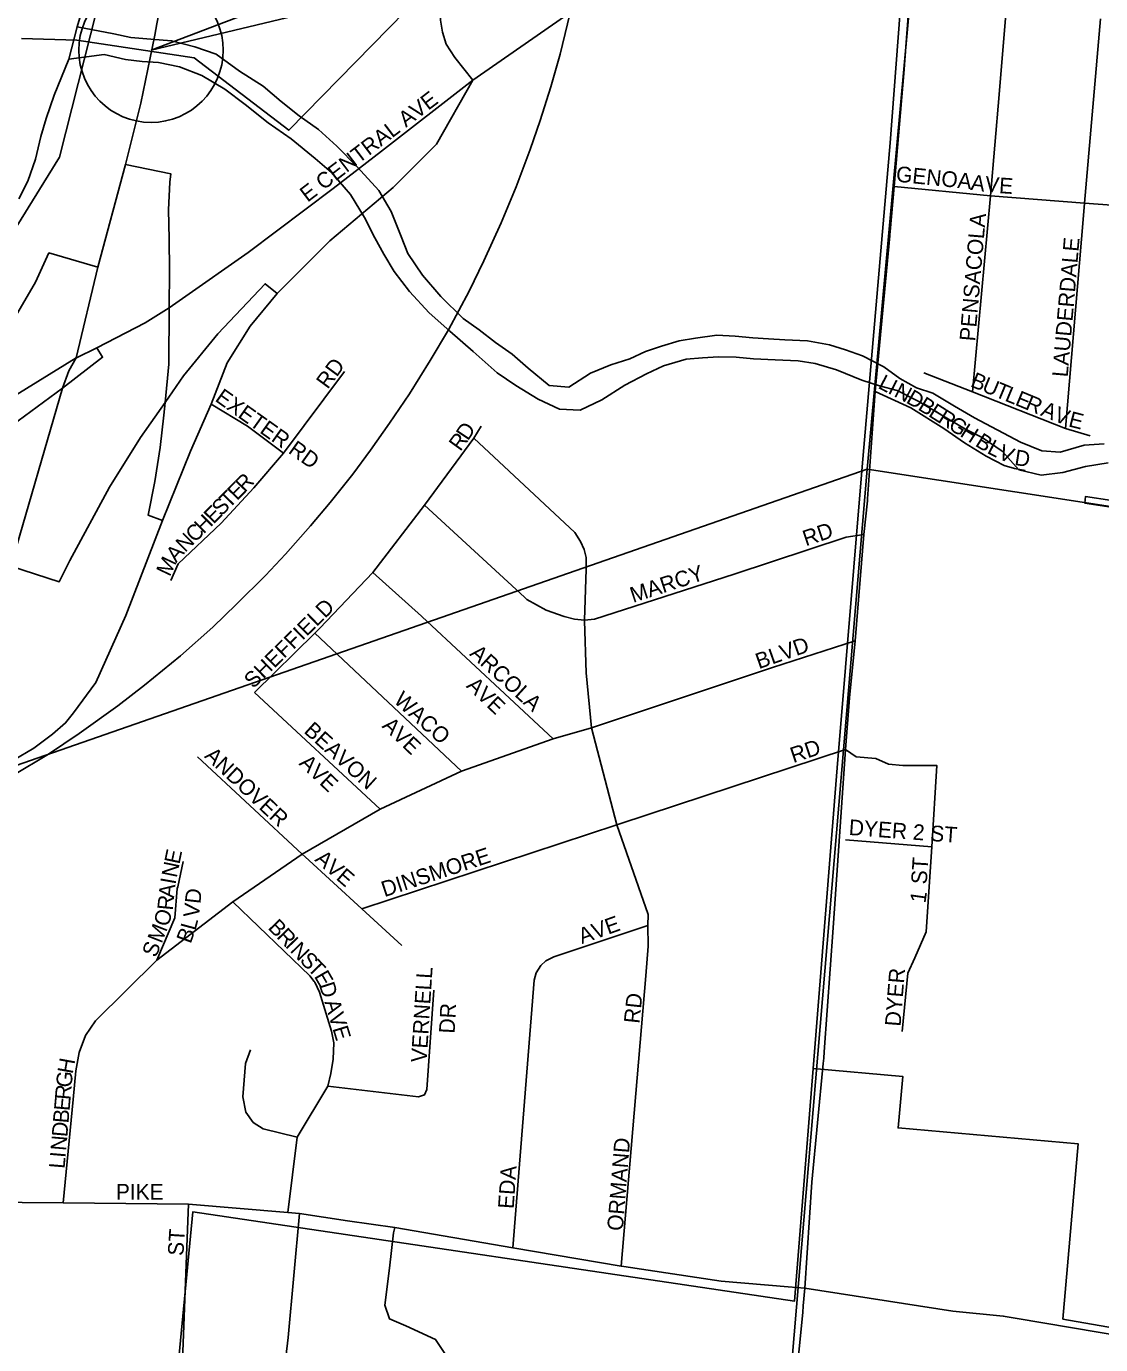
# Model space of a CAD drawing. Extents: x -209 to 4852, y 0 to 905.
# Drawn here: x 505.3 to 518.26, y 261.1 to 277 of the extents above; entities that cross this region are included whole.
import ezdxf

# ---------------------------------------------------------------- set-up
doc = ezdxf.new("R2010")
doc.units = 0
for name, color, linetype in [('GM_X_Airport_Location_Class_2', 7, 'Continuous'), ('GM_X_Airport_Location_Class_3', 7, 'Continuous'), ('GM_X_County_Road', 7, 'Continuous'), ('GM_X_County_Road_Text', 7, 'Continuous'), ('GM_X_County_Subdivision_Text', 7, 'Continuous'), ('GM_X_Interstate_Location', 7, 'Continuous'), ('GM_X_Major_Lake', 7, 'Continuous'), ('GM_X_Minor_River', 7, 'Continuous'), ('GM_X_Rail_Line', 7, 'Continuous'), ('GM_X_Rail_Line_Text', 7, 'Continuous'), ('GM_X_Township_Text', 7, 'Continuous'), ('GM_X_US_Location', 7, 'Continuous'), ('GM_X_US_Route', 7, 'Continuous'), ('SH_Text', 7, 'Continuous')]:
    doc.layers.add(name, color=color, linetype=linetype)

msp = doc.modelspace()

# ---------------------------------------------------------------- linework, layer by layer
at = {"layer": 'GM_X_Airport_Location_Class_2'}
for points in [[(510.682, 276.351), (512.37, 277.526), (513.786, 278.834), (515.257, 280.142), (516.225, 280.826)], [(517.032, 276.181), (517.176, 277.923), (517.181, 277.978)], [(510.682, 276.351), (510.467, 276.626), (510.361, 276.786), (510.317, 276.933), (510.292, 277.077), (510.296, 277.434), (510.322, 277.841)], [(518.05, 274.719), (518.062, 274.869), (518.255, 277.091)], [(506.942, 271.041), (507.279, 271.877), (507.527, 272.443), (507.722, 272.94), (507.999, 273.386), (508.325, 273.779), (508.957, 274.412), (509.723, 275.057), (510.247, 275.582), (510.682, 276.351)], [(510.682, 276.351), (509.582, 275.496)], [(516.712, 272.591), (516.93, 274.958), (517.032, 276.181)], [(509.582, 275.496), (509.001, 275.045), (507.973, 274.272), (507.182, 273.718)], [(515.765, 275.071), (516.93, 274.958), (518.062, 274.869), (518.665, 274.825)], [(517.833, 272.148), (518.05, 274.719)], [(507.182, 273.718), (507.02, 273.605), (506.731, 273.426), (506.148, 273.122), (505.902, 273.003)], [(505.902, 273.003), (505.899, 273.001), (504.972, 272.432)], [(507.039, 270.316), (507.131, 270.516), (507.65, 271.009), (508.042, 271.435), (508.4, 271.851), (509.137, 272.837)], [(516.126, 272.821), (516.712, 272.591), (517.833, 272.148), (518.129, 272.062)], [(515.536, 272.596), (515.967, 272.4), (516.364, 272.149), (516.615, 271.975), (516.878, 271.816), (517.092, 271.702), (517.217, 271.666), (517.345, 271.641)], [(507.527, 272.443), (507.966, 272.176), (508.4, 271.851)], [(508.837, 269.74), (509.477, 270.413), (510.1, 271.225), (510.694, 272.033), (510.786, 272.178)], [(512.03, 269.829), (512.03, 269.836), (512.05, 270.452), (512.052, 270.593), (512.025, 270.691), (511.983, 270.788), (511.914, 270.896), (510.694, 272.033)], [(510.1, 271.225), (511.309, 270.113)], [(504.181, 267.746), (504.255, 267.765), (504.621, 267.902), (505.144, 268.148), (505.388, 268.293), (505.615, 268.461), (505.771, 268.598), (505.868, 268.719), (506.135, 269.086), (506.498, 269.893), (506.942, 271.041)], [(511.309, 270.113), (511.337, 270.087), (511.567, 269.959), (511.784, 269.883), (511.912, 269.851), (512.03, 269.836), (512.151, 269.848), (513.835, 270.393), (515.188, 270.839), (515.4, 270.871)], [(510.065, 269.886), (509.477, 270.413)], [(511.653, 268.405), (510.074, 269.877), (510.065, 269.886)], [(512.474, 262.043), (512.77, 265.547), (512.797, 265.904), (512.795, 266.153), (512.797, 266.284), (512.42, 267.366), (512.114, 268.539), (512.05, 269.202), (512.03, 269.829)], [(508.052, 268.965), (508.78, 269.679), (508.837, 269.74)], [(510.547, 268.015), (508.78, 269.679)], [(505.743, 262.805), (505.863, 264.053), (505.896, 264.4), (505.937, 264.619), (506.011, 264.825), (506.134, 265.003), (506.874, 265.733), (507.79, 266.439), (508.625, 267.014), (509.566, 267.557), (510.547, 268.015), (511.653, 268.405), (512.114, 268.539), (514.297, 269.264), (515.294, 269.589)], [(509.566, 267.557), (508.052, 268.965)], [(508.663, 266.98), (508.625, 267.014), (507.361, 268.189)], [(512.457, 267.378), (515.181, 268.275)], [(515.863, 264.876), (515.93, 265.578), (516.014, 265.764), (516.152, 266.077), (516.22, 267.104), (516.282, 268.082), (515.872, 268.082), (515.697, 268.099), (515.546, 268.167), (515.308, 268.19), (515.181, 268.275)], [(509.344, 266.355), (512.42, 267.366), (512.457, 267.378)], [(515.181, 267.187), (516.22, 267.104)], [(507.124, 266.621), (507.189, 266.925)], [(509.826, 265.912), (509.344, 266.355), (508.663, 266.98)], [(506.874, 265.733), (507.091, 266.247), (507.119, 266.601), (507.124, 266.621)], [(508.771, 265.479), (508.719, 265.547), (507.79, 266.439)], [(511.167, 262.265), (511.423, 265.492), (511.447, 265.58), (511.503, 265.67), (511.564, 265.726), (511.66, 265.776), (512.795, 266.153)], [(508.453, 262.692), (508.564, 263.6), (508.934, 264.213), (508.972, 264.366), (508.998, 264.54), (509.008, 264.736), (508.981, 264.879), (508.833, 265.347), (508.778, 265.47), (508.771, 265.479)], [(508.934, 264.213), (510.028, 264.085), (510.102, 264.109), (510.129, 264.174), (510.214, 265.374)], [(497.772, 264.73), (498.092, 264.608), (499.518, 263.953), (500.869, 263.334), (501.741, 262.94), (502.023, 262.883), (502.736, 262.863), (503.261, 262.828), (505.743, 262.805), (507.256, 262.792), (508.453, 262.692), (508.594, 262.677), (509.173, 262.591), (509.742, 262.508), (511.167, 262.265), (512.474, 262.043), (512.507, 262.038)], [(508.564, 263.6), (508.154, 263.699), (508.034, 263.778), (507.946, 263.901), (507.908, 264.085), (507.94, 264.487), (508.002, 264.652)], [(507.248, 262.589), (507.256, 262.792)], [(512.507, 262.038), (513.68, 261.863), (514.489, 261.793)]]:
    msp.add_lwpolyline(points, dxfattribs=at)
at = {"layer": 'GM_X_County_Road'}
msp.add_line((505.912, 276.995), (505.81, 276.606), dxfattribs=at)
for points in [[(518.3, 271.966), (518.057, 271.948), (517.767, 271.862), (517.547, 271.882), (517.291, 271.986), (516.735, 272.278), (516.495, 272.42), (516.233, 272.577), (516.037, 272.642), (515.834, 272.752), (515.64, 272.893), (515.384, 273.027), (515.181, 273.1), (514.985, 273.157), (514.72, 273.208), (514.447, 273.221), (514.25, 273.232), (514.06, 273.243), (513.848, 273.263), (513.629, 273.275), (513.37, 273.241), (513.172, 273.207), (512.958, 273.143), (512.767, 273.078), (512.576, 272.99), (512.347, 272.919), (512.102, 272.817), (511.841, 272.647), (511.606, 272.667), (511.352, 272.877), (511.158, 273.048), (510.956, 273.189), (510.762, 273.338), (510.567, 273.478), (510.299, 273.742), (510.077, 273.998), (509.9, 274.26), (509.82, 274.467), (509.697, 274.767), (509.55, 275.021), (509.29, 275.308), (509.045, 275.556), (508.821, 275.758), (508.589, 275.923), (508.372, 276.094), (508.156, 276.281), (507.871, 276.462), (507.587, 276.665), (507.331, 276.754), (507.051, 276.828), (506.801, 276.848), (506.559, 276.868), (506.355, 276.91), (505.912, 276.995)], [(505.81, 276.606), (506.236, 276.661), (506.493, 276.603), (506.697, 276.576), (506.894, 276.565), (507.144, 276.514), (507.415, 276.41), (507.692, 276.245), (507.939, 276.057), (508.216, 275.839), (508.493, 275.643), (508.784, 275.409), (508.978, 275.237), (509.208, 274.974), (509.377, 274.697), (509.501, 274.451), (509.611, 274.251), (509.736, 274.043), (509.921, 273.803), (510.159, 273.547), (510.405, 273.322), (510.688, 273.08), (510.979, 272.823), (511.204, 272.667), (511.474, 272.502), (511.729, 272.382), (511.98, 272.37), (512.24, 272.494), (512.517, 272.672), (512.777, 272.811), (512.984, 272.906), (513.259, 272.985), (513.456, 273.004), (513.646, 273.015), (513.859, 273.011), (514.071, 272.992), (514.329, 272.979), (514.609, 272.966), (514.813, 272.932), (515.07, 272.858), (515.378, 272.731), (515.59, 272.666), (515.801, 272.608), (516.064, 272.474), (516.334, 272.316), (516.626, 272.143), (516.829, 272.04), (517.069, 271.876), (517.269, 271.651), (517.541, 271.585), (517.8, 271.618), (518.074, 271.689), (518.348, 271.737)]]:
    msp.add_lwpolyline(points, dxfattribs=at)
at = {"layer": 'GM_X_County_Road_Text'}
for points in [[(514.489, 261.793), (514.688, 261.776), (516.475, 261.501), (517.082, 261.441), (517.249, 261.412)], [(517.249, 261.412), (518.895, 261.132), (520.387, 260.873), (521.669, 260.651), (522.843, 260.448), (522.897, 260.437), (524.533, 260.114)]]:
    msp.add_lwpolyline(points, dxfattribs=at)
at = {"layer": 'GM_X_County_Subdivision_Text'}
for points in [[(515.713, 274.476), (515.714, 274.485), (515.718, 274.526), (515.765, 275.071), (515.884, 276.432), (516.002, 278.04), (516.142, 279.935), (516.225, 280.826)], [(515.445, 271.302), (515.536, 272.596), (515.713, 274.476)], [(515.087, 266.936), (515.126, 267.519), (515.181, 268.275), (515.227, 268.898), (515.294, 269.589), (515.4, 270.871), (515.444, 271.278), (515.445, 271.302)], [(514.916, 264.553), (514.923, 264.628), (515.032, 266.124), (515.087, 266.936)], [(514.67, 261.564), (514.688, 261.776), (514.774, 263.056), (514.909, 264.487), (514.916, 264.553)], [(514.314, 257.541), (514.377, 258.296), (514.525, 260.08), (514.663, 261.484), (514.67, 261.564)]]:
    msp.add_lwpolyline(points, dxfattribs=at)
at = {"layer": 'GM_X_Major_Lake'}
msp.add_line((505.81, 276.606), (505.912, 276.995), dxfattribs=at)
for points in [[(505.912, 276.995), (506.014, 277.351), (505.913, 277.589), (505.668, 277.495), (505.459, 277.643), (505.495, 277.94), (505.725, 278.08), (505.969, 278.128), (506.192, 278.307), (506.213, 278.558), (506.21, 278.801), (506.215, 279.075), (506.212, 279.289), (506.202, 279.548), (506.207, 279.807), (506.183, 280.135), (506.157, 280.379), (506.131, 280.585), (506.068, 280.868), (506.026, 281.059), (505.986, 281.311), (505.901, 281.625), (505.83, 281.908)], [(505.208, 274.922), (505.318, 275.133), (505.407, 275.398), (505.473, 275.671), (505.538, 275.89), (505.635, 276.17), (505.81, 276.606)]]:
    msp.add_lwpolyline(points, dxfattribs=at)
at = {"layer": 'GM_X_Minor_River'}
for points in [[(503.083, 292.205), (517.218, 291.054), (515.439, 271.658), (494.708, 264.441), (495.483, 270.631), (498.242, 270.7), (500.117, 270.96), (502.378, 271.539), (503.263, 272.257), (504.716, 273.844), (505.7, 275.423), (506.518, 278.665), (506.24, 281.617), (506.092, 282.589), (506.012, 284.393), (505.676, 286.665)], [(517.218, 291.054), (537.772, 289.267), (535.846, 268.527), (515.439, 271.658)], [(494.708, 264.441), (515.439, 271.658), (513.823, 252.487), (492.971, 244.015)], [(515.439, 271.658), (535.846, 268.527), (534.233, 247.886), (513.823, 252.487)]]:
    msp.add_lwpolyline(points, close=True, dxfattribs=at)
at = {"layer": 'GM_X_Rail_Line'}
for points in [[(506.942, 271.041), (506.767, 271.104), (506.849, 271.512), (506.913, 271.919), (506.958, 272.312), (506.972, 272.465), (507.015, 272.925), (507.02, 273.605), (507.023, 274.054), (507.021, 274.437), (507.013, 274.786), (507.029, 275.122), (507.042, 275.222), (506.495, 275.336)], [(506.162, 274.095), (505.571, 274.267), (505.41, 273.915), (505.027, 273.26), (504.55, 272.683), (504.215, 272.323), (504.391, 272.075)], [(505.111, 270.488), (505.693, 270.299), (505.821, 270.558), (506.302, 271.442), (506.677, 272.042), (506.972, 272.465), (507.195, 272.785), (507.606, 273.29), (508.177, 273.895), (508.325, 273.779)], [(506.148, 273.122), (506.218, 273.01), (505.735, 272.635), (504.89, 272.017), (504.573, 271.733), (504.39, 271.508), (504.236, 271.253), (504.078, 270.931), (503.985, 270.648), (503.939, 270.349), (503.936, 270.099), (503.92, 269.32), (503.908, 269.022), (503.87, 268.812), (503.836, 268.674), (504.47, 268.478)]]:
    msp.add_lwpolyline(points, dxfattribs=at)
at = {"layer": 'GM_X_Rail_Line_Text'}
for points in [[(506.847, 276.897), (506.874, 277.032), (506.947, 277.427), (507.124, 278.784), (507.191, 280.245), (507.13, 281.769), (507.081, 282.658), (506.993, 284.207), (506.908, 285.729), (506.807, 287.43), (506.753, 288.775), (506.731, 290.315), (506.785, 291.683), (506.859, 293.151), (506.976, 294.462), (507.012, 294.859)], [(505.81, 272.846), (505.899, 273.001), (506.162, 274.095), (506.495, 275.336), (506.679, 276.076), (506.847, 276.897)], [(504.238, 267.71), (504.255, 267.765), (504.47, 268.478), (505.111, 270.488), (505.735, 272.635), (505.81, 272.846)]]:
    msp.add_lwpolyline(points, dxfattribs=at)
at = {"layer": 'GM_X_Township_Text'}
for points in [[(508.232, 259.252), (508.291, 259.795), (508.457, 261.184), (508.594, 262.677)], [(506.908, 258.542), (507.18, 260.906), (507.248, 262.589)], [(509.742, 262.508), (509.728, 262.443), (509.68, 262.018), (509.624, 261.573), (509.68, 261.406), (509.874, 261.323), (510.235, 261.156), (510.346, 260.99), (510.43, 260.74), (510.43, 260.379), (510.374, 259.628), (510.374, 259.184), (510.402, 258.906), (510.513, 258.628), (510.707, 258.323), (511.04, 257.906)]]:
    msp.add_lwpolyline(points, dxfattribs=at)
at = {"layer": 'GM_X_US_Location'}
for points in [[(505.239, 276.856), (505.907, 276.835), (507.322, 276.623), (508.465, 275.747), (510.473, 277.806), (510.486, 277.327), (512.095, 278.778), (512.354, 278.483), (516.025, 282.023), (516.207, 282.027), (516.009, 279.412), (515.718, 275.598), (515.379, 271.686), (515.077, 268.055), (514.788, 264.427), (514.565, 261.622), (507.308, 262.699), (506.908, 258.542), (506.893, 258.388), (507.029, 258.362), (506.166, 249.27), (505.633, 243.664), (498.996, 241.277)], [(505.239, 276.856), (505.907, 276.835), (507.322, 276.623), (508.465, 275.747), (510.473, 277.806), (510.486, 277.327), (512.095, 278.778), (512.354, 278.483), (516.025, 282.023), (516.207, 282.027), (516.009, 279.412), (515.718, 275.598), (515.379, 271.686), (515.077, 268.055), (514.788, 264.427), (515.869, 264.333), (515.814, 263.71), (517.984, 263.52), (517.801, 261.404), (522.051, 260.662)], [(524.494, 260.216), (524.814, 263.61), (524.263, 263.766), (523.682, 264.295), (523.277, 265.246), (522.812, 266.245), (522.629, 267.314), (522.654, 268.53), (522.621, 269.519), (522.46, 270.186), (519.551, 270.698), (519.598, 271.015), (518.065, 271.25), (518.076, 271.33), (518.392, 271.281), (518.859, 277.34)]]:
    msp.add_lwpolyline(points, dxfattribs=at)
at = {"layer": 'GM_X_US_Route'}
msp.add_lwpolyline([(505.135, 267.963), (505.564, 268.219), (505.935, 268.468), (506.402, 268.805), (506.723, 269.051), (507.159, 269.408), (507.546, 269.753), (507.832, 270.028), (508.183, 270.377), (508.424, 270.633), (508.726, 270.976), (508.961, 271.257), (509.238, 271.598), (509.45, 271.887), (509.68, 272.213), (509.919, 272.569), (510.171, 272.97), (510.389, 273.341), (510.639, 273.808), (510.816, 274.172), (511.026, 274.629), (511.208, 275.065), (511.377, 275.515), (511.497, 275.864), (511.624, 276.27), (511.738, 276.665), (512.06, 278.003)], dxfattribs=at)
at = {"layer": 'SH_Text'}
msp.add_lwpolyline([(506.802, 276.714), (575.875, 303.008), (605.554, 303.008), (605.554, 293.141), (575.882, 293.229)], close=True, dxfattribs=at)
msp.add_circle((506.802, 276.714), 0.871, dxfattribs=at)

# ---------------------------------------------------------------- texts
at = {"layer": 'GM_X_Airport_Location_Class_3'}
for s, height, rotation, p in [('E CENTRAL AVE', 0.18939, 37.2852, (508.69, 274.873)), ('GENOA', 0.1894, 354.1768, (515.782, 275.129)), ('A', 0.189, 352.5036, (516.683, 275.029)), ('V', 0.189, 354.3721, (516.855, 275.007)), ('E', 0.189, 356.1278, (517.027, 274.99)), ('PENSACOLA', 0.1894, 85.1208, (516.743, 273.197)), ('LAUDERDALE', 0.1894, 85.0816, (517.859, 272.764)), ('RD', 0.1894, 53.7411, (508.933, 272.615)), ('L', 0.189, 332.4819, (515.561, 272.642)), ('B', 0.189, 337.5221, (516.675, 272.66)), ('EXETER RD', 0.1894, 324.6374, (507.563, 272.489)), ('I', 0.189, 332.4573, (515.679, 272.581)), ('N', 0.189, 332.473, (515.753, 272.542)), ('D', 0.189, 330.1982, (515.899, 272.466)), ('U', 0.189, 337.5479, (516.814, 272.603)), ('T', 0.189, 337.5441, (516.968, 272.539)), ('L', 0.189, 337.5441, (517.091, 272.488)), ('B', 0.189, 327.6909, (516.042, 272.384)), ('E', 0.189, 337.5188, (517.214, 272.437)), ('R', 0.189, 337.5515, (517.337, 272.386)), ('E', 0.189, 327.5602, (516.169, 272.304)), ('R', 0.189, 327.5876, (516.281, 272.233)), ('A', 0.189, 337.5247, (517.522, 272.31)), ('V', 0.189, 338.7945, (517.681, 272.245)), ('E', 0.189, 345.6378, (517.859, 272.177)), ('D', 0.189, 56.4585, (510.625, 271.993)), ('G', 0.189, 327.5707, (516.408, 272.152)), ('H', 0.189, 327.5811, (516.549, 272.063)), ('R', 0.189, 54.0869, (510.533, 271.865)), ('B', 0.189, 328.1177, (516.733, 271.946)), ('L', 0.189, 333.1615, (516.877, 271.857)), ('V', 0.189, 336.5716, (517.007, 271.792)), ('D', 0.189, 351.0472, (517.21, 271.711)), ('E', 0.189, 45.1008, (507.837, 271.272)), ('R', 0.189, 46.1637, (507.934, 271.369)), ('T', 0.189, 45.0831, (507.743, 271.177)), ('E', 0.189, 45.1008, (507.554, 270.988)), ('S', 0.189, 45.0966, (507.648, 271.083)), ('H', 0.189, 45.0927, (507.437, 270.87)), ('N', 0.189, 45.1082, (507.213, 270.646)), ('C', 0.189, 45.0858, (507.331, 270.764)), ('RD', 0.1894, 18.4349, (514.7, 270.728)), ('A', 0.189, 48.6187, (507.105, 270.523)), ('M', 0.189, 64.6244, (507.027, 270.354)), ('MARCY', 0.1894, 18.0863, (512.617, 270.044)), ('SHEFFIELD', 0.1894, 44.4665, (508.036, 269.003)), ('BLVD', 0.1894, 19.3628, (514.134, 269.245)), ('ARCOLA', 0.1894, 317.8636, (510.635, 269.42)), ('AVE', 0.1894, 316.3964, (510.595, 269.034)), ('WACO', 0.1894, 317.9093, (509.719, 268.854)), ('BEAVON', 0.1894, 317.7911, (508.635, 268.487)), ('AVE', 0.1894, 316.3964, (509.578, 268.55)), ('RD', 0.1894, 18.4386, (514.55, 268.111)), ('ANDOVER', 0.1894, 316.7728, (507.436, 268.187)), ('AVE', 0.1894, 316.3964, (508.578, 268.1)), ('DYER 2 ST', 0.1894, 355.7938, (515.214, 267.246)), ('E', 0.189, 78.2239, (507.145, 266.885)), ('DINSMORE', 0.1894, 18.1882, (509.617, 266.494)), ('N', 0.189, 78.3815, (507.112, 266.722)), ('AVE', 0.1894, 319.1875, (508.768, 266.938)), ('ST', 0.1894, 86.4262, (516.159, 266.646)), ('A', 0.189, 83.6695, (507.079, 266.478)), ('I', 0.189, 79.9414, (507.097, 266.641)), ('D', 0.189, 83.8104, (507.397, 266.409)), ('R', 0.189, 84.6253, (507.065, 266.33)), ('V', 0.189, 83.4229, (507.378, 266.242)), ('1', 0.189, 81.8743, (516.143, 266.416)), ('O', 0.189, 72.9115, (507.008, 266.129)), ('AVE', 0.1894, 19.6509, (511.999, 265.928)), ('M', 0.189, 68.3839, (506.929, 265.928)), ('B', 0.189, 69.5292, (507.279, 265.925)), ('L', 0.189, 74.9423, (507.337, 266.084)), ('B', 0.189, 314.0726, (508.203, 266.119)), ('R', 0.189, 314.0383, (508.308, 266.011)), ('S', 0.189, 68.3761, (506.862, 265.757)), ('I', 0.189, 314.0713, (508.412, 265.903)), ('N', 0.189, 314.0573, (508.47, 265.843)), ('S', 0.189, 314.0528, (508.586, 265.724)), ('T', 0.189, 313.86, (508.679, 265.628)), ('VERNELL', 0.1894, 86.369, (510.126, 264.496)), ('DYER', 0.1894, 85.483, (515.843, 264.93)), ('E', 0.189, 300.0126, (508.764, 265.541)), ('D', 0.189, 287.8821, (508.826, 265.436)), ('RD', 0.1894, 83.9946, (512.693, 264.964)), ('A', 0.189, 286.9903, (508.892, 265.23)), ('DR', 0.1894, 86.989, (510.464, 264.846)), ('V', 0.189, 286.9958, (508.94, 265.071)), ('E', 0.189, 286.9943, (508.989, 264.911)), ('H', 0.189, 79.7362, (505.857, 264.355)), ('G', 0.189, 84.7917, (505.843, 264.193)), ('R', 0.189, 85.1375, (505.83, 264.044)), ('E', 0.189, 85.1402, (505.819, 263.911)), ('B', 0.189, 85.1375, (505.806, 263.762)), ('D', 0.189, 85.142, (505.792, 263.596)), ('N', 0.189, 85.1389, (505.778, 263.43)), ('ORMAND', 0.1894, 85.3884, (512.492, 262.463)), ('I', 0.189, 85.1379, (505.771, 263.346)), ('L', 0.189, 85.132, (505.759, 263.214)), ('EDA', 0.1894, 86.0574, (511.176, 262.73)), ('PIKE', 0.1894, 0, (506.378, 262.846))]:
    msp.add_text(s, height=height, rotation=rotation, dxfattribs=at).set_placement(p)
at = {"layer": 'GM_X_Interstate_Location'}
msp.add_text('ST', height=0.1894, rotation=86.4254, dxfattribs=at).set_placement((507.192, 262.163))

doc.saveas('drawing.dxf')
